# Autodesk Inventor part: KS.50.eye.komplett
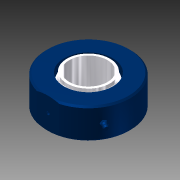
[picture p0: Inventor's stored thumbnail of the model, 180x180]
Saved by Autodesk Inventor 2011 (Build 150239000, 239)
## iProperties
Created: 2010-10
Part Number: KS.50.eye.komplett
Document SubType Name: Modeling
Designer: tribel
Density: 1 g/cm^3
Author: tribel
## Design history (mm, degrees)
derived "KS50eye.iam"
body "Solid1"
node "Lagerhus50.ipt:1"
node "Kule50HO.ipt:1"
sketch "Smørenippel.ipt:1"
